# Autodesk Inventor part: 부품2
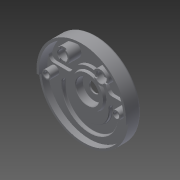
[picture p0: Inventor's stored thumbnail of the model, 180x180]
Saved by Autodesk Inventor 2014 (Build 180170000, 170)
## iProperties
Created: 2015-04
Part Number: 부품2
Material: Generic
Document SubType Name: Modeling
Designer: Administrator
Density: 1 g/cm^3
Appearance: Default
Author: Administrator
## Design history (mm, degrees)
sketch "스케치3"
  geometry: C1 r 95 at (0, 0); 1 further point
  constraints: 1 centre point, 1 coincident
  dimensions: "d1" = 190 diameter of C1
extrude "돌출1" new body sketch "스케치3" distance "d2" = 32; taper "d3" = 0 deg
sketch "스케치4"
  geometry: L1 (0, 0)-(-94.638, -8.28); L2 (0, 0)-(145.059, 0); L3 (0, 0)-(94.638, -8.28); L4 (0, 0)-(186.6, 0); A1 r 95 centre (0, 0) between (94.638, -8.28) and (-94.638, -8.28) reference
  constraints: 8 end point, 2 horizontal, 2 point on circle
  dimensions: "d4" = 175 deg angle of L1 L2; "d5" = 5 deg angle of L3 L4
extrude "돌출2" cut sketch "스케치4" distance "d6" = 5; taper "d7" = 0 deg
sketch "스케치5"
  geometry: L1 (-76.916, 12)-(-47.117, 12); L2 (47.117, 12)-(76.916, 12); A1 r 42 centre (0, 0) between (38.056, 17.769) and (-38.056, 17.769); A2 r 10 centre (-47.117, 22) between (-47.117, 12) and (-38.056, 17.769); A3 r 10 centre (47.117, 22) between (38.056, 17.769) and (47.117, 12); A4 r 90 centre (0, 0) between (86.53, 24.75) and (-86.53, 24.75); A5 r 10 centre (-76.916, 22) between (-86.53, 24.75) and (-76.916, 12); A6 r 10 centre (76.916, 22) between (76.916, 12) and (86.53, 24.75); 4 further points
  constraints: 16 point on circle, 8 tangent, 6 centre point, 5 point on line, 4 end point, 1 coincident, 1 collinear, 1 equal radius
  dimensions: "d8" = 84 diameter of A1; "d10" = 10 radius of A2; "d11" = 10 radius of A3; "d12" = 180 diameter of A4; "d13" = 10 radius of A5
extrude "돌출3" cut sketch "스케치5" distance "d14" = 25; taper "d15" = 0 deg
sketch "스케치6"
  geometry: C1 r 42 at (0, 0); A1 r 95 centre (0, 0) between (94.638, -8.28) and (-94.638, -8.28) reference
  constraints: 1 centre point, 1 coincident
  dimensions: "d16" = 84 diameter of C1
extrude "돌출4" cut sketch "스케치6" distance "d18" = 8; taper "d19" = 0 deg
sketch "스케치7"
  geometry: C1 r 90 at (0, 0); A1 r 90 centre (0, 0) between (86.53, 24.75) and (-86.53, 24.75) reference
  constraints: 1 centre point, 1 coincident
  dimensions: "d20" = 180 diameter of C1
extrude "돌출5" cut sketch "스케치7" distance "d21" = 13; taper "d22" = 0 deg
sketch "스케치8"
  geometry: C1 r 90 at (0, 0)
  constraints: 1 centre point
  dimensions: "d24" = 180 diameter of C1
extrude "돌출6" cut sketch "스케치8" distance "d25" = 10; taper "d26" = 0 deg
sketch "스케치9"
  geometry: C1 r 42 at (0, 0); A1 r 42 centre (0, 0) between (38.056, 17.769) and (-38.056, 17.769) reference
  constraints: 1 centre point, 1 coincident
  dimensions: "d27" = 84 diameter of C1
extrude "돌출7" join sketch "스케치9" distance "d28" = 10; taper "d29" = 0 deg
sketch "스케치10"
  geometry: L1 (-47.117, 12)-(-76.916, 12) reference; L2 (0, 0)-(0, 52); L3 (0, 52)-(40, 52); L4 (0, 52)-(-40, 52); C1 r 15 at (-40, 52); C2 r 15 at (40, 52); A1 r 90 centre (0, 0) between (86.53, 24.75) and (-86.53, 24.75) reference
  constraints: 6 end point, 2 centre point, 2 coincident, 2 perpendicular, 1 collinear
  dimensions: "d30" = 52 distance of L2.start L2.end; "d31" = 40 distance of L2.end L3.end; "d32" = 40 distance of L2.end L4.end; "d33" = 30 diameter of C1; "d34" = 30 diameter of C2
extrude "돌출8" join sketch "스케치10" distance "d35" = 25; taper "d36" = 0 deg
hole "구멍1" diameter "d39" = 20; stored, may be unused: countersink angle "d43" = 90 deg, drill point angle "d45" = 118 deg; dims "d37" = 10, "d38" = 10, "d40" = 6, "d41" = 4, "d42" = 2, "d44" = 8
hole "구멍2" diameter "d48" = 20; stored, may be unused: countersink angle "d52" = 90 deg, drill point angle "d54" = 118 deg; dims "d46" = 10, "d47" = 10, "d49" = 6, "d50" = 4, "d51" = 2, "d53" = 8
sketch "스케치11"
  geometry: L1 (-6, -19.375)-(6, -19.375); L2 (6, -19.375)-(6, 19.375); L3 (6, 19.375)-(-6, 19.375); L4 (-6, 19.375)-(-6, -19.375); L5 (-6, -19.375)-(6, 19.375); L6 (6, -19.375)-(-6, 19.375); C1 r 15 at (0, 0) reference; 1 further point
  constraints: 12 end point, 2 midpoint, 2 parallel, 1 horizontal, 1 perpendicular
  dimensions: "d55" = 12 distance of L2.end L3.end
extrude "돌출9" cut sketch "스케치11" distance "d56" = 3; taper "d57" = 0 deg
sketch "스케치12"
  geometry: L1 (-23.656, 6)-(23.656, 6); L2 (23.656, 6)-(23.656, -6); L3 (23.656, -6)-(-23.656, -6); L4 (-23.656, -6)-(-23.656, 6); L5 (-23.656, 6)-(23.656, -6); L6 (23.656, 6)-(-23.656, -6); C1 r 15 at (0, 0) reference; 1 further point
  constraints: 12 end point, 2 midpoint, 2 parallel, 1 horizontal, 1 perpendicular
  dimensions: "d58" = 12 distance of L3.end L1.start
extrude "돌출10" cut sketch "스케치12" distance "d59" = 3; taper "d60" = 0 deg
hole "구멍3" diameter "d63" = 23; stored, may be unused: countersink angle "d67" = 90 deg, drill point angle "d69" = 118 deg; dims "d61" = 10, "d62" = 10, "d64" = 6, "d65" = 50, "d66" = 15, "d68" = 8
sketch "스케치13"
  geometry: C1 r 42 at (0, 0) reference; C2 r 35 at (0, 0)
  constraints: 1 centre point, 1 coincident
  dimensions: "d70" = 70 diameter of C2
extrude "돌출11" cut sketch "스케치13" distance "d71" = 10; taper "d72" = 0 deg
sketch "스케치14"
  geometry: C1 r 9 at (-74, 0); C2 r 9 at (74, 0); A1 r 42 centre (0, 0) between (38.056, 17.769) and (-38.056, 17.769) reference; A2 r 74 centre (0, 0) between (-74, 0) and (74, 0)
  constraints: 3 centre point, 3 coincident, 2 point on circle
  dimensions: "d73" = 148 diameter of A2; "d74" = 18 diameter of C1; "d75" = 18 diameter of C2
extrude "돌출12" join sketch "스케치14" stored distance "d76" = 14; taper "d77" = 0 deg
sketch "스케치15"
  geometry: C1 r 9.007 at (4.528, 46.96)
  constraints: 1 centre point
extrude "돌출13" join sketch "스케치15" distance "d78" = 14; taper "d79" = 0 deg
sketch "스케치16"
  geometry: C1 r 9.007 at (4.528, -46.96) reference; C2 r 9 at (74, 0) reference; C3 r 9 at (-74, 0) reference; C4 r 35 at (0, 0) reference; C5 r 90 at (0, 0); A1 r 42 centre (0, 0) between (38.056, 17.769) and (-38.056, 17.769) reference
  constraints: 1 centre point, 1 coincident
  dimensions: "d80" = 180 diameter of C5
extrude "돌출14" join sketch "스케치16" stored distance "d81" = 14; taper "d82" = 0 deg
sketch "스케치17"
  geometry: L1 (-47.117, 12)-(-76.916, 12); L2 (-65, 0)-(-68.026, 0); L3 (35, 0)-(28.284, 0); L4 (-28.284, 0)-(-35, 0); L5 (47.117, 12)-(76.916, 12); C1 r 15 at (-40, 52) reference; C2 r 15 at (40, 52) reference; A1 r 35 centre (0, 0) between (-35, 0) and (35, 0) reference; A2 r 90 centre (0, 0) between (-89.196, 12) and (89.196, 12) reference; A3 r 28.284 centre (0, 0) between (28.284, 0) and (-28.284, 0); A4 r 42 centre (0, 0) between (38.056, 17.769) and (-38.056, 17.769); A5 r 90 centre (0, 0) between (86.53, 24.75) and (-86.53, 24.75); A6 r 10 centre (-76.916, 22) between (-86.53, 24.75) and (-76.916, 12); A7 r 10 centre (-47.117, 22) between (-47.117, 12) and (-38.056, 17.769); A8 r 10 centre (47.117, 22) between (38.056, 17.769) and (47.117, 12); A9 r 10 centre (76.916, 22) between (76.916, 12) and (86.53, 24.75); 3 further points
  constraints: 22 point on circle, 10 end point, 8 tangent, 7 centre point, 6 point on line, 4 parallel, 3 coincident, 3 horizontal, 2 equal radius, 1 horizontal alignment, 1 other
  dimensions: "d86" = 84 diameter of A4; "d88" = 10 radius of A6; "d89" = 10 radius of A8
extrude "돌출15" join sketch "스케치17" stored distance "d90" = 14; taper "d91" = 0 deg
sketch "스케치18"
  geometry: L1 (32, 46)-(26.252, 46) reference; L2 (26.252, 58)-(32, 58) reference; L3 (48, 58)-(53.748, 58) reference; L4 (53.748, 46)-(48, 46) reference; L5 (-34, 44)-(-34, 38.252) reference; L6 (-46, 38.252)-(-46, 44) reference; L7 (-46, 60)-(-46, 65.748) reference; L8 (-34, 65.748)-(-34, 60) reference; L9 (-76.916, 12)-(-47.117, 12) reference; L10 (47.117, 12)-(76.916, 12) reference; A1 r 10 centre (40, 52) between (48, 58) and (32, 58) reference; A2 r 10 centre (40, 52) between (32, 46) and (48, 46) reference; A3 r 10 centre (-40, 52) between (-46, 60) and (-46, 44) reference; A4 r 10 centre (-40, 52) between (-34, 44) and (-34, 60) reference; A5 r 10 centre (-76.916, 22) between (-86.53, 24.75) and (-76.916, 12) reference; A6 r 10 centre (-47.117, 22) between (-47.117, 12) and (-38.056, 17.769) reference; A7 r 42 centre (0, 0) between (38.056, 17.769) and (-38.056, 17.769) reference; A8 r 10 centre (47.117, 22) between (38.056, 17.769) and (47.117, 12) reference; A9 r 10 centre (76.916, 22) between (76.916, 12) and (86.53, 24.75) reference; A10 r 15 centre (-40, 52) between (-34, 38.252) and (-46, 38.252) reference; A11 r 15 centre (40, 52) between (26.252, 46) and (26.252, 58) reference; A12 r 90 centre (0, 0) between (-86.53, 24.75) and (86.53, 24.75) reference
extrude "돌출16" cut sketch "스케치18" distance "d92" = 24; taper "d93" = 0 deg
hole "구멍4" diameter "d96" = 11; stored, may be unused: countersink angle "d100" = 90 deg, drill point angle "d102" = 118 deg; dims "d94" = 10, "d95" = 10, "d97" = 6, "d98" = 18, "d99" = 11, "d101" = 8
hole "구멍5" diameter "d105" = 11; stored, may be unused: countersink angle "d109" = 90 deg, drill point angle "d111" = 118 deg; dims "d103" = 10, "d104" = 10, "d106" = 6, "d107" = 18, "d108" = 11, "d110" = 8
hole "구멍6" diameter "d114" = 20; stored, may be unused: countersink angle "d118" = 90 deg, drill point angle "d120" = 118 deg; dims "d112" = 10, "d113" = 10, "d115" = 6, "d116" = 18, "d117" = 11, "d119" = 8
hole "구멍7" diameter "d123" = 20; stored, may be unused: countersink angle "d127" = 90 deg, drill point angle "d129" = 118 deg; dims "d121" = 10, "d122" = 10, "d124" = 6, "d125" = 18, "d126" = 11, "d128" = 8
sketch "스케치19"
  geometry: L1 (-47.117, 12)-(-76.916, 12) reference; L2 (0, 0)-(0, -19); L3 (59, -14)-(58.788, -14); L4 (-58.788, -14)-(-59, -14); L5 (0, -19)-(-29.394, -19); A1 r 59 centre (0, -19) between (-58.788, -14) and (58.788, -14); A2 r 41 centre (0, -19) between (-40.694, -14) and (40.694, -14); A3 r 9.153 centre (-49.847, -14) between (-40.876, -15.818) and (-58.891, -15.41); A4 r 9.153 centre (49.847, -14) between (58.891, -15.41) and (40.876, -15.818)
  constraints: 14 point on circle, 8 end point, 4 centre point, 2 coincident, 2 parallel, 2 perpendicular, 2 point on line, 2 other
  dimensions: "d130" = 19 distance of L2.start L2.end; "d131" = 118 diameter of A1; "d132" = 82 diameter of A2
extrude "돌출17" cut sketch "스케치19" distance "d134" = 7; taper "d135" = 0 deg
sketch "스케치20"
  geometry: L1 (35, 13)-(35, 18) reference; L2 (-35, 13)-(35, 13) reference; L3 (-35, 13)-(-35, 18) reference; L4 (35, 18)-(33.18, 13); L5 (33.18, 13)-(33.18, 18); L6 (33.18, 18)-(35, 18); L7 (0, -3.6)-(0, 21.6) reference; 1 further point
  constraints: 6 end point, 1 perpendicular, 1 point on line
revolve "회전1" sketch "스케치20" stored, may be unused: angle "d137" = 90 deg
fillet "모깎기1" dims "d138" = 5, "d139" = 0.3
chamfer "모따기1" distance "d140" = 1; stored, may be unused: second distance "d141" = 2, angle "d142" = 45 deg
sketch "스케치21"
  geometry: L1 (0, 0)-(72, 0); L2 (0, 0)-(72, 0); L3 (-36.062, 36.062)-(-50.912, 50.912); L4 (36.062, 36.062)-(50.912, 50.912); C1 r 12.5 at (0, 0) reference; A1 r 51 centre (0, 0) between (36.062, 36.062) and (-36.062, 36.062); A2 r 72 centre (0, 0) between (50.912, 50.912) and (-50.912, 50.912)
  constraints: 8 end point, 4 point on circle, 2 centre point, 2 coincident, 2 horizontal
  dimensions: "d144" = 102 diameter of A1
extrude "돌출18" join sketch "스케치21" distance "d147" = 5; taper "d148" = 0 deg
fillet "모깎기2" dims "d149" = 3, "d150" = 5
sketch "스케치22"
  geometry: L1 (44.564, 50.81)-(35.938, 42.183) reference; L2 (-35.938, 42.183)-(-44.564, 50.81) reference; L3 (-35.938, 42.183)-(-44.564, 50.81); L4 (35.938, 42.183)-(44.564, 50.81); A1 r 55.416 centre (0, 0) between (35.938, 42.183) and (-35.938, 42.183); 1 further point
  constraints: 4 end point, 2 collinear, 2 point on circle, 1 centre point, 1 coincident, 1 horizontal alignment, 1 point on line
fillet "모깎기3" dims "d151" = 1
node "솔리드1"
other parameters: "d85" = 12, "d133" = 5, "d143" = 144, "d145" = 45 deg, "d146" = 135 deg
